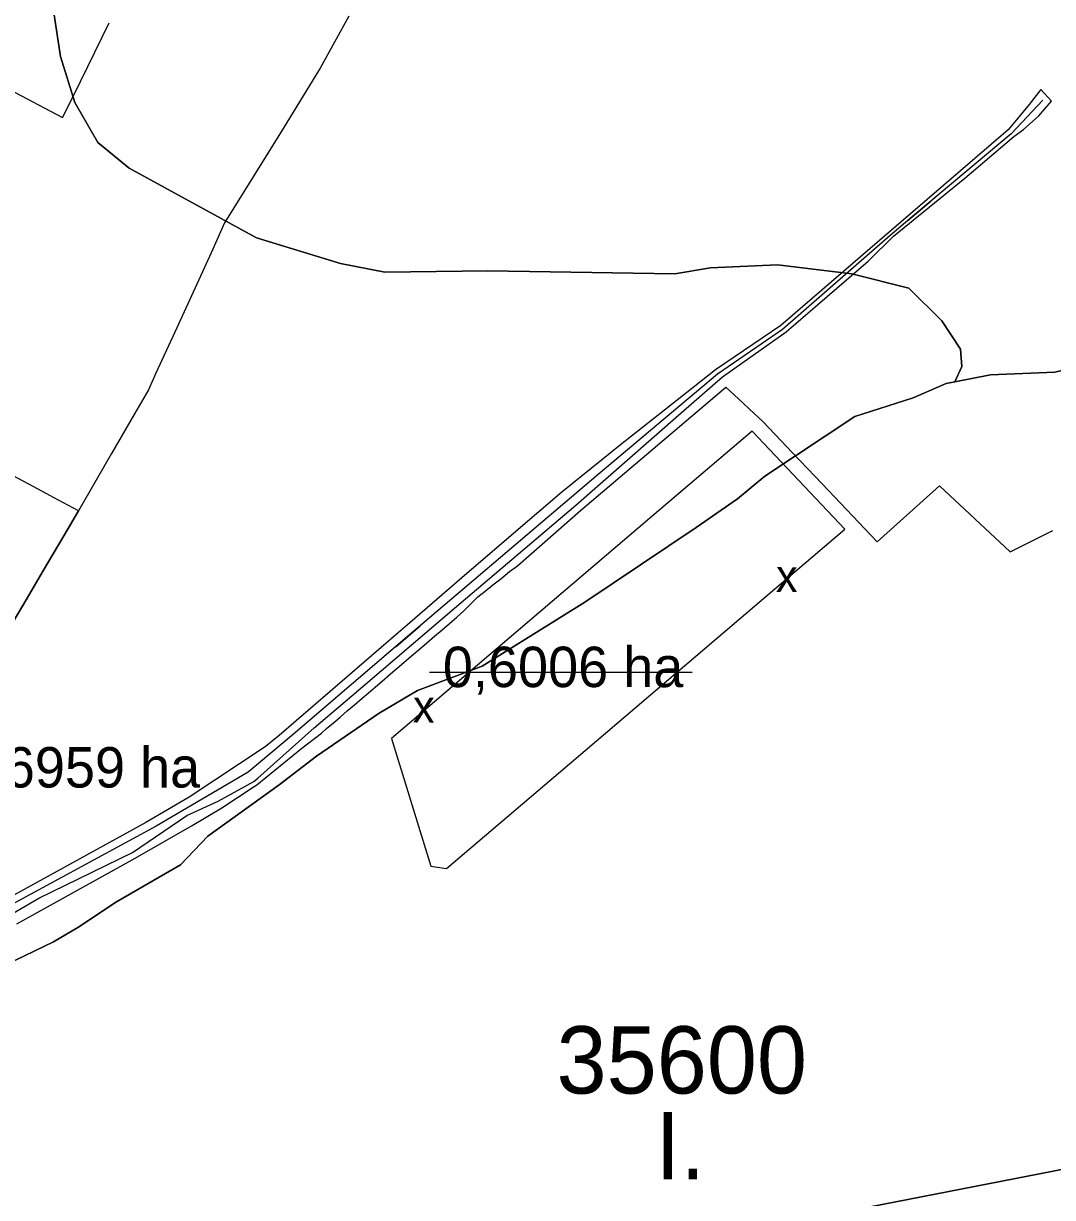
# Model space of a CAD drawing. Extents: x -555509 to -553014, y -1186753 to -1182560.
# Drawn here: x -554748.1 to -554442.6, y -1185549 to -1185200.4 of the extents above; entities that cross this region are included whole.
import ezdxf

# ---------------------------------------------------------------- set-up
doc = ezdxf.new("R2010")
doc.units = 0
for name, color, linetype in [('I_2_Leg_HV', 7, 'Continuous'), ('LEG_1_ZCU', 7, 'Continuous'), ('LEG_6_ZPF', 7, 'Continuous'), ('Level 29', 7, 'Continuous'), ('Level 52', 7, 'Continuous'), ('ZABOR_ke_zruseni', 7, 'Continuous'), ('zatrubnene_toky', 7, 'Continuous'), ('ZPF_I_TR_OCHRANY', 7, 'Continuous'), ('ZPF_zabor', 7, 'Continuous')]:
    doc.layers.add(name, color=color, linetype=linetype)

msp = doc.modelspace()

# ---------------------------------------------------------------- linework, layer by layer
at = {"layer": 'I_2_Leg_HV'}
for points in [[(-554620.16, -1185374.01), (-554584.15, -1185343.5), (-554552.85, -1185316.09), (-554540.6, -1185305.36), (-554521.74, -1185291.99), (-554497.35, -1185271.02), (-554489.84, -1185263.62), (-554468.69, -1185246.34), (-554454.15, -1185233.99), (-554451.29, -1185231.91), (-554446.68, -1185227.84), (-554442.98, -1185223.48), (-554446.15, -1185220.07)], [(-554446.15, -1185220.07), (-554449.59, -1185224.49), (-554455.82, -1185232.07), (-554498.97, -1185269.16), (-554523.34, -1185290.16), (-554542.74, -1185303.24), (-554557.8, -1185315.23), (-554570.88, -1185325.6), (-554588.35, -1185339.59)], [(-554588.35, -1185339.59), (-554602, -1185351.33), (-554618.68, -1185365.64), (-554633.44, -1185378.36), (-554636.89, -1185381.33), (-554672.25, -1185411.89), (-554676.42, -1185415.26), (-554698.96, -1185430.19)], [(-554690.31, -1185431.4), (-554679.72, -1185425.57), (-554678.56, -1185424.53), (-554661.85, -1185409.57), (-554650.64, -1185400.08), (-554620.16, -1185374.01)], [(-554698.96, -1185430.19), (-554711.78, -1185437.68), (-554777.58, -1185473.79)], [(-554715.8, -1185446.65), (-554699.63, -1185435.59), (-554690.31, -1185431.4)], [(-554775.16, -1185478.6), (-554743.55, -1185460.15), (-554715.8, -1185446.65)]]:
    msp.add_lwpolyline(points, dxfattribs=at)
at = {"layer": 'LEG_6_ZPF'}
for p, q in [((-554475.5, -1185288.75), (-554485.25, -1185279)), ((-554474.25, -1185307.38), (-554471.69, -1185306.88)), ((-554528.06, -1185334.88), (-554501.38, -1185317.13)), ((-554536.12, -1185341.63), (-554528.06, -1185334.88)), ((-554739.19, -1185473.12), (-554732, -1185468.88)), ((-554750.69, -1185478.63), (-554739.19, -1185473.12))]:
    msp.add_line(p, q, dxfattribs=at)
for points in [[(-554732.88, -1185223.88), (-554737.12, -1185210.25), (-554739.19, -1185196.62), (-554741.31, -1185179.75), (-554743.88, -1185157.63), (-554743.88, -1185123.75), (-554741.75, -1185106.75), (-554740.06, -1185096.62)], [(-554739.19, -1185196.62), (-554737.12, -1185210.25), (-554732.88, -1185223.88), (-554726.06, -1185235.75), (-554716.75, -1185243.38), (-554679, -1185264.13), (-554654, -1185271.75), (-554640.88, -1185274.25), (-554610.31, -1185273.88), (-554554.81, -1185274.75), (-554544.19, -1185273), (-554524.25, -1185272.13), (-554502.19, -1185274.75), (-554485.25, -1185279), (-554475.5, -1185288.75), (-554470, -1185297.13), (-554469.56, -1185302.25), (-554471.69, -1185306.88)], [(-554716.75, -1185243.38), (-554726.06, -1185235.75), (-554732.88, -1185223.88)], [(-554524.25, -1185272.13), (-554544.19, -1185273), (-554554.81, -1185274.75), (-554610.31, -1185273.88), (-554640.88, -1185274.25), (-554654, -1185271.75), (-554679, -1185264.13), (-554716.75, -1185243.38)], [(-554485.25, -1185279), (-554502.19, -1185274.75), (-554524.25, -1185272.13)], [(-554471.69, -1185306.88), (-554469.56, -1185302.25), (-554470, -1185297.13), (-554475.5, -1185288.75)], [(-554471.69, -1185306.88), (-554461.06, -1185304.75), (-554442, -1185304), (-554415.31, -1185297.62), (-554400.88, -1185296.38), (-554375, -1185292.5), (-554354.69, -1185290.75)], [(-554501.38, -1185317.13), (-554484, -1185311.63), (-554474.25, -1185307.38)], [(-554631.12, -1185398.5), (-554612, -1185391.25), (-554581.5, -1185372.25), (-554548.44, -1185350.12), (-554536.12, -1185341.63)], [(-554672.25, -1185426.5), (-554661.19, -1185418), (-554642.56, -1185405.25), (-554631.12, -1185398.5)], [(-554701.5, -1185450.25), (-554693.44, -1185441.75), (-554672.25, -1185426.5)], [(-554732, -1185468.88), (-554720.56, -1185461.25), (-554701.5, -1185450.25)], [(-554434.38, -1185539.63), (-554532.31, -1185558.75), (-554542.06, -1185560.5)]]:
    msp.add_lwpolyline(points, dxfattribs=at)
at = {"layer": 'Level 29'}
for points in [[(-554739.19, -1185196.62), (-554737.12, -1185210.25), (-554732.88, -1185223.88), (-554726.06, -1185235.75), (-554716.75, -1185243.38), (-554679, -1185264.13), (-554654, -1185271.75), (-554640.88, -1185274.25), (-554610.31, -1185273.88), (-554554.81, -1185274.75), (-554544.19, -1185273), (-554524.25, -1185272.13), (-554502.19, -1185274.75), (-554485.25, -1185279), (-554475.5, -1185288.75), (-554470, -1185297.13), (-554469.56, -1185302.25), (-554471.69, -1185306.88)], [(-554246.56, -1185309.88), (-554256.31, -1185301), (-554273.25, -1185293.38), (-554280.06, -1185291.25), (-554313.12, -1185287), (-554342.38, -1185289.13), (-554354.69, -1185290.75), (-554375, -1185292.5), (-554400.88, -1185296.38), (-554415.31, -1185297.62), (-554442, -1185304), (-554461.06, -1185304.75), (-554471.69, -1185306.88)], [(-554750.69, -1185478.63), (-554739.19, -1185473.12), (-554732, -1185468.88), (-554720.56, -1185461.25), (-554701.5, -1185450.25), (-554693.44, -1185441.75), (-554672.25, -1185426.5), (-554661.19, -1185418), (-554642.56, -1185405.25), (-554631.12, -1185398.5), (-554612, -1185391.25), (-554581.5, -1185372.25), (-554548.44, -1185350.12), (-554536.12, -1185341.63), (-554528.06, -1185334.88), (-554501.38, -1185317.13), (-554484, -1185311.63), (-554474.25, -1185307.38), (-554471.69, -1185306.88)], [(-554668.81, -1185666), (-554639.12, -1185660.5), (-554632.38, -1185658), (-554627.31, -1185654.12), (-554620.06, -1185645.62), (-554612.44, -1185633.75), (-554606.94, -1185620.25), (-554605.25, -1185610), (-554600.56, -1185598.25), (-554592.94, -1185586.38), (-554589.56, -1185582.88), (-554586.19, -1185579.13), (-554572.19, -1185570.25), (-554542.06, -1185560.5), (-554532.31, -1185558.75), (-554434.38, -1185539.63), (-554415.75, -1185534.63), (-554383.06, -1185521), (-554358.88, -1185506.63), (-554332.19, -1185482.88)]]:
    msp.add_lwpolyline(points, dxfattribs=at)
at = {"layer": 'Level 52'}
for points in [[(-554651.54, -1185198.32), (-554660.04, -1185213.75), (-554661.31, -1185215.81), (-554671.87, -1185232.89), (-554682.43, -1185249.97), (-554688.42, -1185259.67), (-554691.95, -1185267.5), (-554694.99, -1185274.23)], [(-554694.99, -1185274.23), (-554703.22, -1185292.14), (-554708.82, -1185304.31), (-554711.08, -1185309.23), (-554715.19, -1185316.37), (-554721.98, -1185328.15), (-554728.42, -1185339.33), (-554731.79, -1185345.18), (-554734.88, -1185350.42), (-554742.18, -1185362.81), (-554744.55, -1185366.82), (-554747.05, -1185371.06), (-554752.81, -1185380.83)], [(-554698.05, -1185438.6), (-554689.29, -1185433.35), (-554679.91, -1185427.23), (-554678.86, -1185426.55), (-554665.52, -1185415.64), (-554663.8, -1185414.32), (-554661.71, -1185412.73), (-554659.7, -1185411.15), (-554658.14, -1185409.81), (-554656.13, -1185408.09), (-554654.12, -1185406.38), (-554652.03, -1185404.58), (-554649.92, -1185402.78), (-554647.63, -1185400.82), (-554645.75, -1185399.21), (-554643.68, -1185397.44), (-554641.63, -1185395.68), (-554639.15, -1185393.56), (-554635.22, -1185390.2), (-554632.91, -1185388.21), (-554630.58, -1185386.22), (-554628.38, -1185384.34), (-554626.11, -1185382.4), (-554623.88, -1185380.49), (-554621.67, -1185378.59), (-554619.48, -1185376.72), (-554618.5, -1185375.88), (-554617.32, -1185374.72), (-554613.22, -1185370.7), (-554611.05, -1185369.01), (-554608.79, -1185367.12), (-554606.46, -1185365.33), (-554603.81, -1185363.19), (-554601.51, -1185361.48), (-554582.75, -1185345.07), (-554539.62, -1185308.46), (-554537.2, -1185310.71), (-554534.53, -1185313.19), (-554532.62, -1185314.97), (-554528.56, -1185318.75), (-554519.81, -1185327.95), (-554511.06, -1185337.16), (-554494.74, -1185354.34), (-554476.17, -1185337.77), (-554455.26, -1185357.31), (-554443.5, -1185351.5), (-554442.56, -1185351.04)], [(-554750.17, -1185467.82), (-554741.93, -1185463.25), (-554714.96, -1185448.24), (-554698.05, -1185438.6)]]:
    msp.add_lwpolyline(points, dxfattribs=at)
at = {"layer": 'ZABOR_ke_zruseni'}
for p, q in [((-554733.33, -1185221.96), (-554722.73, -1185200.26)), ((-554768.86, -1185211.34), (-554736.6, -1185228.38)), ((-554736.6, -1185228.38), (-554733.33, -1185221.96)), ((-554504.31, -1185350.64), (-554531.78, -1185321.49)), ((-554627.57, -1185393.02), (-554549.58, -1185393.02))]:
    msp.add_line(p, q, dxfattribs=at)
for points in [[(-554531.78, -1185321.49), (-554556.23, -1185342.33), (-554638.92, -1185412.79)], [(-554638.92, -1185412.79), (-554627.18, -1185450.64), (-554622.56, -1185451.39), (-554584.08, -1185418.61), (-554504.31, -1185350.64)]]:
    msp.add_lwpolyline(points, dxfattribs=at)
at = {"layer": 'zatrubnene_toky'}
for points in [[(-554445.49, -1185223.21), (-554454.96, -1185233.2), (-554483.05, -1185256.78), (-554490.83, -1185263.4), (-554522.76, -1185291.29), (-554542.15, -1185304.6), (-554577.54, -1185334.32), (-554633.5, -1185381.96), (-554668, -1185411.5), (-554681.46, -1185422.71), (-554708.78, -1185438.76), (-554758.85, -1185465.95), (-554795.57, -1185486.43), (-554821.6, -1185495.33), (-554849.36, -1185501.68)], [(-554485.47, -1185258.84), (-554478.76, -1185253.18)], [(-554637.55, -1185385.43), (-554630.36, -1185379.29)]]:
    msp.add_lwpolyline(points, dxfattribs=at)
at = {"layer": 'ZPF_I_TR_OCHRANY'}
for points in [[(-554246.56, -1185309.88), (-554256.31, -1185301), (-554273.25, -1185293.38), (-554280.06, -1185291.25), (-554313.12, -1185287), (-554342.38, -1185289.13), (-554354.69, -1185290.75), (-554375, -1185292.5), (-554400.88, -1185296.38), (-554415.31, -1185297.62), (-554442, -1185304), (-554461.06, -1185304.75), (-554471.69, -1185306.88)], [(-554471.69, -1185306.88), (-554474.25, -1185307.38), (-554484, -1185311.63), (-554501.38, -1185317.13), (-554528.06, -1185334.88), (-554536.12, -1185341.63), (-554548.44, -1185350.12), (-554581.5, -1185372.25), (-554612, -1185391.25), (-554631.12, -1185398.5), (-554642.56, -1185405.25), (-554661.19, -1185418), (-554672.25, -1185426.5), (-554693.44, -1185441.75), (-554701.5, -1185450.25), (-554720.56, -1185461.25), (-554732, -1185468.88), (-554739.19, -1185473.12), (-554750.69, -1185478.63)], [(-554668.81, -1185666), (-554639.12, -1185660.5), (-554632.38, -1185658), (-554627.31, -1185654.12), (-554620.06, -1185645.62), (-554612.44, -1185633.75), (-554606.94, -1185620.25), (-554605.25, -1185610), (-554600.56, -1185598.25), (-554592.94, -1185586.38), (-554589.56, -1185582.88), (-554586.19, -1185579.13), (-554572.19, -1185570.25), (-554542.06, -1185560.5), (-554532.31, -1185558.75), (-554434.38, -1185539.63), (-554415.75, -1185534.63), (-554383.06, -1185521), (-554358.88, -1185506.63), (-554332.19, -1185482.88)]]:
    msp.add_lwpolyline(points, dxfattribs=at)
at = {"layer": 'ZPF_zabor'}
for p, q in [((-554746.53, -1185337.24), (-554756.64, -1185331.95)), ((-554741.42, -1185340.01), (-554746.53, -1185337.24)), ((-554739.23, -1185341.16), (-554741.42, -1185340.01)), ((-554731.79, -1185345.18), (-554739.23, -1185341.16)), ((-554734.88, -1185350.42), (-554731.79, -1185345.18)), ((-554742.18, -1185362.81), (-554734.88, -1185350.42)), ((-554744.55, -1185366.82), (-554742.18, -1185362.81)), ((-554747.05, -1185371.06), (-554744.55, -1185366.82)), ((-554752.81, -1185380.83), (-554747.05, -1185371.06))]:
    msp.add_line(p, q, dxfattribs=at)

# ---------------------------------------------------------------- texts
at = {"layer": 'LEG_1_ZCU'}
msp.add_text('0,6959 ha', height=12, dxfattribs=at).set_placement((-554767.08, -1185427.31))
at = {"layer": 'Level 29'}
for s, p in [('35600', (-554589.89, -1185518.18)), ('I.', (-554560.58, -1185543.63))]:
    msp.add_text(s, height=20, dxfattribs=at).set_placement(p)
at = {"layer": 'ZABOR_ke_zruseni'}
for p in [(-554524.79, -1185369.22), (-554632.57, -1185407.99)]:
    msp.add_text('x', height=9.63, rotation=359.2857, dxfattribs=at).set_placement(p)
msp.add_text('0,6006 ha', height=12, dxfattribs=at).set_placement((-554623.64, -1185397.5))

doc.saveas('drawing.dxf')
